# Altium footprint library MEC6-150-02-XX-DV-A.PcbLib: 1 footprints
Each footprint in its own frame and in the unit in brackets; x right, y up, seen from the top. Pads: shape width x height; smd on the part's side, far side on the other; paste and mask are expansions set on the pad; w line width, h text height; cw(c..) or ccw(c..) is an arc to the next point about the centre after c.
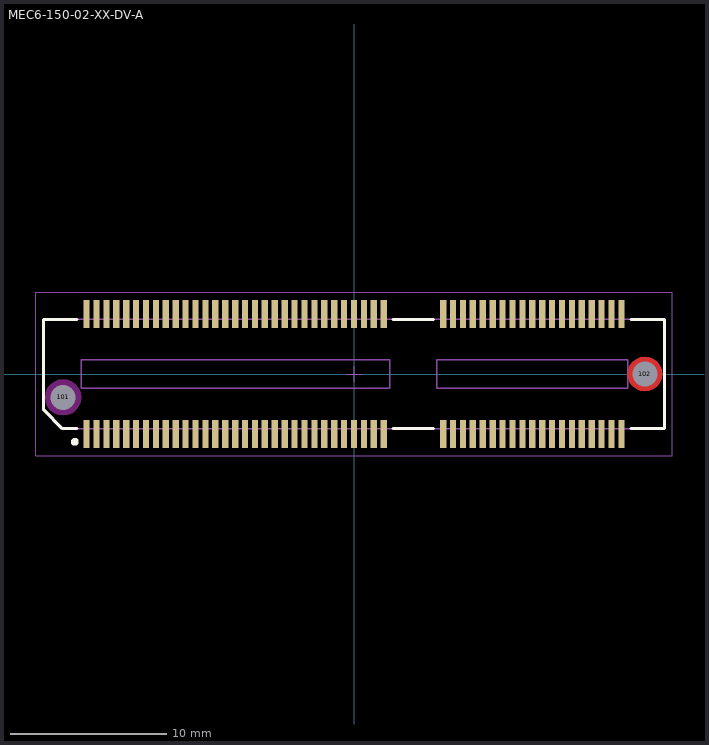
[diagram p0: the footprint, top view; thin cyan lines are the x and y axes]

## MEC6-150-02-XX-DV-A [mm] "0.635mm pitch, 100 pin, micro edge card; vertical, w/alignment pins, SMT"
height 8.65
pads (102):
  rect 0.4x1.8 smd mask+0: 1(-17.145,-3.848) 2(-17.145,3.848) 3(-16.51,-3.848) 4(-16.51,3.848) 5(-15.875,-3.848) 6(-15.875,3.848) 7(-15.24,-3.848) 8(-15.24,3.848) 9(-14.605,-3.848) 10(-14.605,3.848) 11(-13.97,-3.848) 12(-13.97,3.848) 13(-13.335,-3.848) 14(-13.335,3.848) 15(-12.7,-3.848) 16(-12.7,3.848) 17(-12.065,-3.848) 18(-12.065,3.848) 19(-11.43,-3.848) 20(-11.43,3.848) 21(-10.795,-3.848) 22(-10.795,3.848) 23(-10.16,-3.848) 24(-10.16,3.848) 25(-9.525,-3.848) 26(-9.525,3.848) 27(-8.89,-3.848) 28(-8.89,3.848) 29(-8.255,-3.848) 30(-8.255,3.848) 31(-7.62,-3.848) 32(-7.62,3.848) 33(-6.985,-3.848) 34(-6.985,3.848) 35(-6.35,-3.848) 36(-6.35,3.848) 37(-5.715,-3.848) 38(-5.715,3.848) 39(-5.08,-3.848) 40(-5.08,3.848) 41(-4.445,-3.848) 42(-4.445,3.848) 43(-3.81,-3.848) 44(-3.81,3.848) 45(-3.175,-3.848) 46(-3.175,3.848) 47(-2.54,-3.848) 48(-2.54,3.848) 49(-1.905,-3.848) 50(-1.905,3.848) 51(-1.27,-3.848) 52(-1.27,3.848) 53(-0.635,-3.848) 54(-0.635,3.848) 55(0,-3.848) 56(0,3.848) 57(0.635,-3.848) 58(0.635,3.848) 59(1.27,-3.848) 60(1.27,3.848) 61(1.905,-3.848) 62(1.905,3.848) 63(5.715,-3.848) 64(5.715,3.848) 65(6.35,-3.848) 66(6.35,3.848) 67(6.985,-3.848) 68(6.985,3.848) 69(7.62,-3.848) 70(7.62,3.848) 71(8.255,-3.848) 72(8.255,3.848) 73(8.89,-3.848) 74(8.89,3.848) 75(9.525,-3.848) 76(9.525,3.848) 77(10.16,-3.848) 78(10.16,3.848) 79(10.795,-3.848) 80(10.795,3.848) 81(11.43,-3.848) 82(11.43,3.848) 83(12.065,-3.848) 84(12.065,3.848) 85(12.7,-3.848) 86(12.7,3.848) 87(13.335,-3.848) 88(13.335,3.848) 89(13.97,-3.848) 90(13.97,3.848) 91(14.605,-3.848) 92(14.605,3.848) 93(15.24,-3.848) 94(15.24,3.848) 95(15.875,-3.848) 96(15.875,3.848) 97(16.51,-3.848) 98(16.51,3.848) 99(17.145,-3.848) 100(17.145,3.848)
  round 1 hole 1.6 unplated mask+0: 101(-18.644,-1.499) 102(18.644,0)
Top Layer:
  pour cut-out: 19.759,0 19.722,0.287 19.611,0.555 19.435,0.785 19.205,0.961 18.937,1.072 18.65,1.109 18.363,1.072 18.095,0.961 17.865,0.785 17.689,0.555 17.578,0.287 17.541,0 17.578,-0.287 17.689,-0.555 17.865,-0.785 18.095,-0.961 18.363,-1.072 18.65,-1.109 18.937,-1.072 19.205,-0.961 19.435,-0.785 19.611,-0.555 19.722,-0.287
Top Overlay:
  circle w0.25: c-17.9,-4.35 r0.125
  lines w0.2: -17.75,-3.5 -18.7,-3.5 -19.9,-2.3 -19.9,3.5 -17.75,3.5 ; 2.5,-3.5 5.1,-3.5 ; 2.5,3.5 5.1,3.5 ; 17.75,-3.5 19.9,-3.5 19.9,3.5 17.75,3.5
Keep-Out Layer:
  pour cut-out: -17.49,-1.5 -17.53,-1.2 -17.645,-0.92 -17.83,-0.68 -18.07,-0.495 -18.35,-0.38 -18.65,-0.34 -18.95,-0.38 -19.23,-0.495 -19.47,-0.68 -19.655,-0.92 -19.77,-1.2 -19.81,-1.5 -19.77,-1.8 -19.655,-2.08 -19.47,-2.32 -19.23,-2.505 -18.95,-2.62 -18.65,-2.66 -18.35,-2.62 -18.07,-2.505 -17.83,-2.32 -17.645,-2.08 -17.53,-1.8
Mechanical 12:
  lines w0.001: -19.9,-2.3 -19.9,3.5 19.9,3.5 19.9,-3.5 -18.7,-3.5 -19.9,-2.3
Mechanical 13:
  lines w0.1: -19.9,-2.3 -19.9,3.5 19.9,3.5 19.9,-3.5 -18.7,-3.5 -19.9,-2.3 ; -17.5,-0.9 -17.5,0.9 2.3,0.9 2.3,-0.9 -17.5,-0.9 ; 5.3,-0.9 5.3,0.9 17.55,0.9 17.55,-0.9 5.3,-0.9
  text ".Designator" at 0.254,0.254 h1.52
Mechanical 15:
  lines w0.05: -0.5,0 0.5,0 ; 0,-0.5 0,0.5 ; -20.4,-5.25 -20.4,5.25 20.4,5.25 20.4,-5.25 -20.4,-5.25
